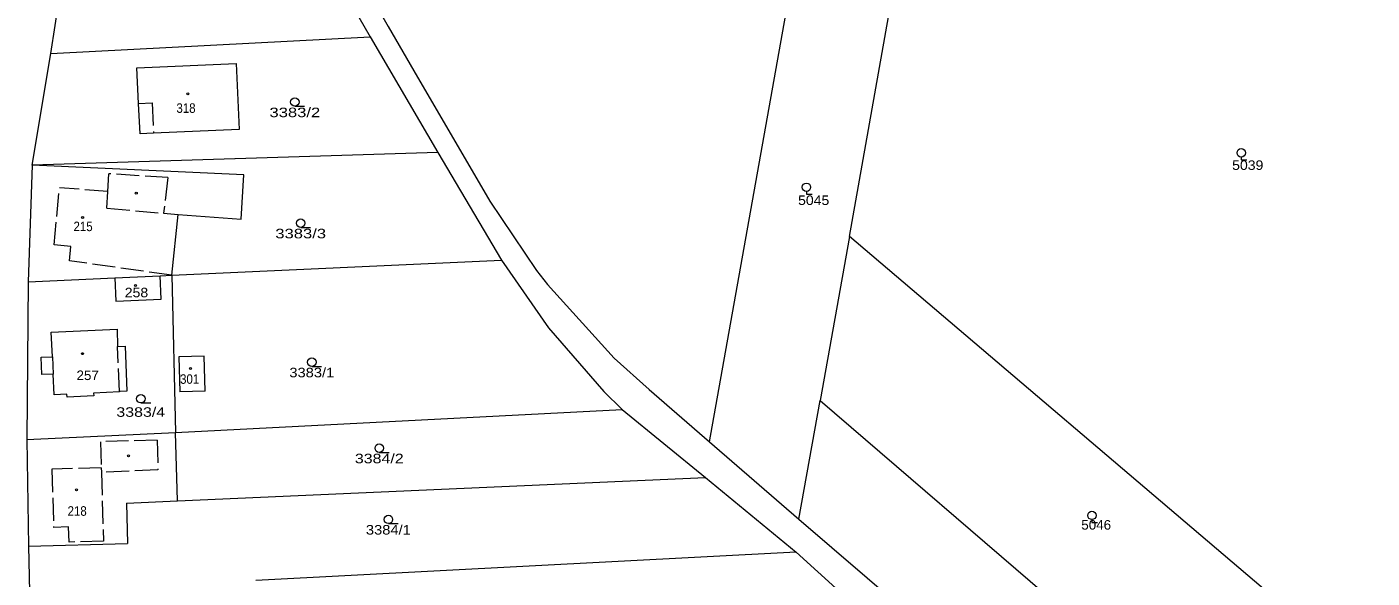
# Model space of a CAD drawing. Extents: x -590528 to -586543, y -1119609 to -1116685.
# Drawn here: x -588604.8 to -588365.2, y -1118121.8 to -1118023.6 of the extents above; entities that cross this region are included whole.
import ezdxf
from ezdxf.enums import TextEntityAlignment as Align

# ---------------------------------------------------------------- set-up
doc = ezdxf.new("R2010")
doc.units = 0
doc.header["$LTSCALE"] = 0.68
doc.linetypes.add('LONG_DASHED', pattern=[7.5, 6, -1.5])
for name, color, linetype, lineweight in [('1', 7, 'Continuous', 13), ('2', 7, 'LONG_DASHED', 13), ('3', 7, 'Continuous', 13), ('6', 7, 'Continuous', 13)]:
    doc.layers.add(name, color=color, linetype=linetype, lineweight=lineweight)

msp = doc.modelspace()

# ---------------------------------------------------------------- linework, layer by layer
at = {"layer": '1'}
for p, q in [((-588562.31, -1117992.56), (-588543.64, -1118025.35)), ((-588600.51, -1118028.32), (-588597.22, -1118006.55)), ((-588600.51, -1118028.32), (-588543.64, -1118025.35)), ((-588543.64, -1118025.35), (-588531.6, -1118045.93)), ((-588531.6, -1118045.93), (-588520.26, -1118065.16)), ((-588603.84, -1118048.19), (-588604.57, -1118068.98)), ((-588566.13, -1118049.94), (-588603.84, -1118048.19)), ((-588566.6, -1118057.83), (-588566.13, -1118049.94)), ((-588578.98, -1118067.82), (-588577.87, -1118057)), ((-588577.87, -1118057), (-588566.6, -1118057.83)), ((-588458.27, -1118060.91), (-588463.5, -1118090.17)), ((-588365.16, -1118140.1), (-588458.27, -1118060.91)), ((-588578.98, -1118067.82), (-588520.26, -1118065.16)), ((-588520.26, -1118065.16), (-588511.85, -1118077.19)), ((-588580.89, -1118072.11), (-588581.08, -1118067.92)), ((-588604.57, -1118068.98), (-588604.79, -1118097.08)), ((-588589.12, -1118068.28), (-588588.93, -1118072.47)), ((-588588.93, -1118072.47), (-588580.89, -1118072.11)), ((-588600.45, -1118077.94), (-588588.71, -1118077.41)), ((-588588.71, -1118077.41), (-588588.63, -1118080.52)), ((-588600.25, -1118082.34), (-588600.45, -1118077.94)), ((-588602.25, -1118082.43), (-588600.25, -1118082.34)), ((-588588.63, -1118080.52), (-588587.28, -1118080.47)), ((-588587.28, -1118080.47), (-588586.96, -1118088.46)), ((-588573.21, -1118082.27), (-588577.71, -1118082.38)), ((-588577.71, -1118082.38), (-588577.55, -1118088.58)), ((-588573.06, -1118088.46), (-588573.21, -1118082.27)), ((-588602.11, -1118085.52), (-588602.25, -1118082.43)), ((-588600.11, -1118085.43), (-588602.11, -1118085.52)), ((-588599.95, -1118089.13), (-588600.11, -1118085.43)), ((-588597.65, -1118089.03), (-588599.95, -1118089.13)), ((-588597.63, -1118089.53), (-588597.65, -1118089.03)), ((-588592.88, -1118089.32), (-588597.63, -1118089.53)), ((-588588.31, -1118088.61), (-588592.9, -1118088.82)), ((-588592.9, -1118088.82), (-588592.88, -1118089.32)), ((-588586.96, -1118088.46), (-588588.31, -1118088.51)), ((-588588.31, -1118088.51), (-588588.31, -1118088.61)), ((-588573.06, -1118088.46), (-588577.55, -1118088.58)), ((-588463.5, -1118090.17), (-588379.4, -1118162.35)), ((-588604.79, -1118097.08), (-588578.34, -1118095.87)), ((-588577.98, -1118108.04), (-588578.34, -1118095.87)), ((-588604.79, -1118097.08), (-588604.48, -1118116.1)), ((-588577.98, -1118108.04), (-588483.93, -1118103.88)), ((-588587.06, -1118108.45), (-588577.98, -1118108.04)), ((-588587.06, -1118108.45), (-588586.86, -1118115.62)), ((-588604.48, -1118116.1), (-588586.86, -1118115.62)), ((-588604.48, -1118116.1), (-588604.34, -1118124.26)), ((-588467.73, -1118117.14), (-588564.01, -1118122.22)), ((-588445.35, -1118137.46), (-588467.73, -1118117.14))]:
    msp.add_line(p, q, dxfattribs=at)
for points in [[(-588535.99, -1117960.26), (-588543.46, -1118018.15), (-588540.46, -1118023.48), (-588535.88, -1118031.38), (-588522.31, -1118054.62)], [(-588483.2, -1118097.51), (-588467.56, -1118009.97), (-588535.99, -1117960.26)], [(-588458.27, -1118060.91), (-588451.28, -1118021.8), (-588449.7, -1118012.92)], [(-588531.6, -1118045.93), (-588603.84, -1118048.19), (-588600.51, -1118028.32)], [(-588522.31, -1118054.62), (-588514.02, -1118066.97), (-588512.05, -1118069.47), (-588500.2, -1118082.57), (-588493.92, -1118088.21), (-588483.2, -1118097.51)], [(-588604.57, -1118068.98), (-588589.12, -1118068.28), (-588581.08, -1118067.92), (-588578.98, -1118067.82)], [(-588578.98, -1118067.82), (-588578.34, -1118095.87), (-588498.76, -1118091.74)], [(-588511.85, -1118077.19), (-588502, -1118088.54), (-588498.76, -1118091.74), (-588483.93, -1118103.88), (-588467.73, -1118117.14)], [(-588483.2, -1118097.51), (-588470.37, -1118108.64), (-588467.28, -1118111.3), (-588463.5, -1118090.17)], [(-588467.28, -1118111.3), (-588449.24, -1118126.81), (-588403.93, -1118165.64)]]:
    msp.add_lwpolyline(points, dxfattribs=at)
msp.add_lwpolyline([(-588585.22, -1118030.87), (-588567.5, -1118030.08), (-588566.97, -1118041.88), (-588582.24, -1118042.53), (-588584.59, -1118042.6), (-588584.89, -1118037.2)], close=True, dxfattribs=at)
at = {"layer": '2'}
for p, q in [((-588590.4, -1118052.92), (-588590.21, -1118049.75)), ((-588579.68, -1118050.43), (-588590.21, -1118049.75)), ((-588579.68, -1118050.43), (-588580.45, -1118056.77)), ((-588599.93, -1118062.41), (-588599, -1118052.23)), ((-588590.4, -1118052.92), (-588599, -1118052.23)), ((-588590.53, -1118055.87), (-588590.4, -1118052.92)), ((-588590.53, -1118055.87), (-588580.45, -1118056.77)), ((-588580.45, -1118056.77), (-588577.87, -1118057)), ((-588596.97, -1118062.68), (-588599.93, -1118062.41)), ((-588597.21, -1118065.27), (-588596.97, -1118062.68)), ((-588578.98, -1118067.82), (-588597.21, -1118065.27)), ((-588600.25, -1118082.34), (-588600.11, -1118085.43)), ((-588588.31, -1118088.51), (-588588.63, -1118080.52)), ((-588581.58, -1118097.19), (-588591.68, -1118097.48)), ((-588591.68, -1118097.48), (-588591.54, -1118102.13)), ((-588581.58, -1118097.19), (-588581.47, -1118102.49)), ((-588591.54, -1118102.13), (-588600.34, -1118102.38)), ((-588600.34, -1118102.38), (-588600.04, -1118112.76)), ((-588581.47, -1118102.49), (-588591.52, -1118102.93)), ((-588597.36, -1118112.68), (-588600.04, -1118112.76)), ((-588597.28, -1118115.36), (-588597.36, -1118112.68)), ((-588591.17, -1118115.18), (-588597.28, -1118115.36))]:
    msp.add_line(p, q, dxfattribs=at)
for points in [[(-588584.89, -1118037.2), (-588582.49, -1118037.09), (-588582.24, -1118042.53)], [(-588591.54, -1118102.13), (-588591.52, -1118102.93), (-588591.17, -1118115.18)]]:
    msp.add_lwpolyline(points, dxfattribs=at)
at = {"layer": '6'}
for p, q in [((-588557.06, -1118037.71), (-588555.31, -1118037.71)), ((-588556.02, -1118059.3), (-588554.27, -1118059.3)), ((-588554.04, -1118084.06), (-588552.29, -1118084.06)), ((-588584.49, -1118090.57), (-588582.74, -1118090.57)), ((-588542.02, -1118099.38), (-588540.27, -1118099.38)), ((-588540.4, -1118112.08), (-588538.65, -1118112.08))]:
    msp.add_line(p, q, dxfattribs=at)
for points in [[(-588388.46, -1118046.76), (-588388.46, -1118047.26), (-588387.46, -1118047.26)], [(-588465.93, -1118052.89), (-588465.93, -1118053.39), (-588464.93, -1118053.39)], [(-588415.06, -1118111.36), (-588415.06, -1118111.86), (-588414.06, -1118111.86)]]:
    msp.add_lwpolyline(points, dxfattribs=at)
for centre, radius in [((-588576.1402, -1118035.5004), 0.175), ((-588557.06, -1118036.96), 0.75), ((-588388.46, -1118046.01), 0.75), ((-588585.3002, -1118053.2004), 0.175), ((-588465.93, -1118052.14), 0.75), ((-588594.8602, -1118057.5604), 0.175), ((-588556.02, -1118058.55), 0.75), ((-588585.4302, -1118069.6604), 0.175), ((-588594.8702, -1118081.8004), 0.175), ((-588575.6402, -1118084.4604), 0.175), ((-588554.04, -1118083.31), 0.75), ((-588584.49, -1118089.82), 0.75), ((-588542.02, -1118098.63), 0.75), ((-588586.7102, -1118100.0004), 0.175), ((-588595.9502, -1118106.0604), 0.175), ((-588540.4, -1118111.33), 0.75), ((-588415.06, -1118110.61), 0.75)]:
    msp.add_circle(centre, radius, dxfattribs=at)

# ---------------------------------------------------------------- texts
at = {"layer": '3'}
for s, width, p in [('318', 0.9, (-588576.45, -1118038.89)), ('3383/2', 1.3, (-588557.0605, -1118039.66)), ('215', 0.9, (-588594.7805, -1118059.97)), ('3383/3', 1.3, (-588556.02, -1118061.25)), ('258', 1.1, (-588585.2705, -1118071.75)), ('257', 1.05, (-588593.961, -1118086.5)), ('3383/1', 1.15, (-588554.04, -1118086.01)), ('301', 0.9, (-588575.8005, -1118087.17)), ('3383/4', 1.25, (-588584.51, -1118093.05)), ('3384/2', 1.25, (-588542.0205, -1118101.33)), ('218', 0.9, (-588595.84, -1118110.68)), ('3384/1', 1.15, (-588540.4, -1118114.03))]:
    msp.add_text(s, height=1.7, dxfattribs=dict(at, width=width)).set_placement(p, align=Align.CENTER)
for s, width, p in [('5039', 1.1, (-588390.093, -1118049.06)), ('5045', 1.1, (-588467.413, -1118055.31)), ('5046', 1.05, (-588416.963, -1118113.15))]:
    msp.add_text(s, height=1.7, dxfattribs=dict(at, width=width)).set_placement(p)

doc.saveas('drawing.dxf')
